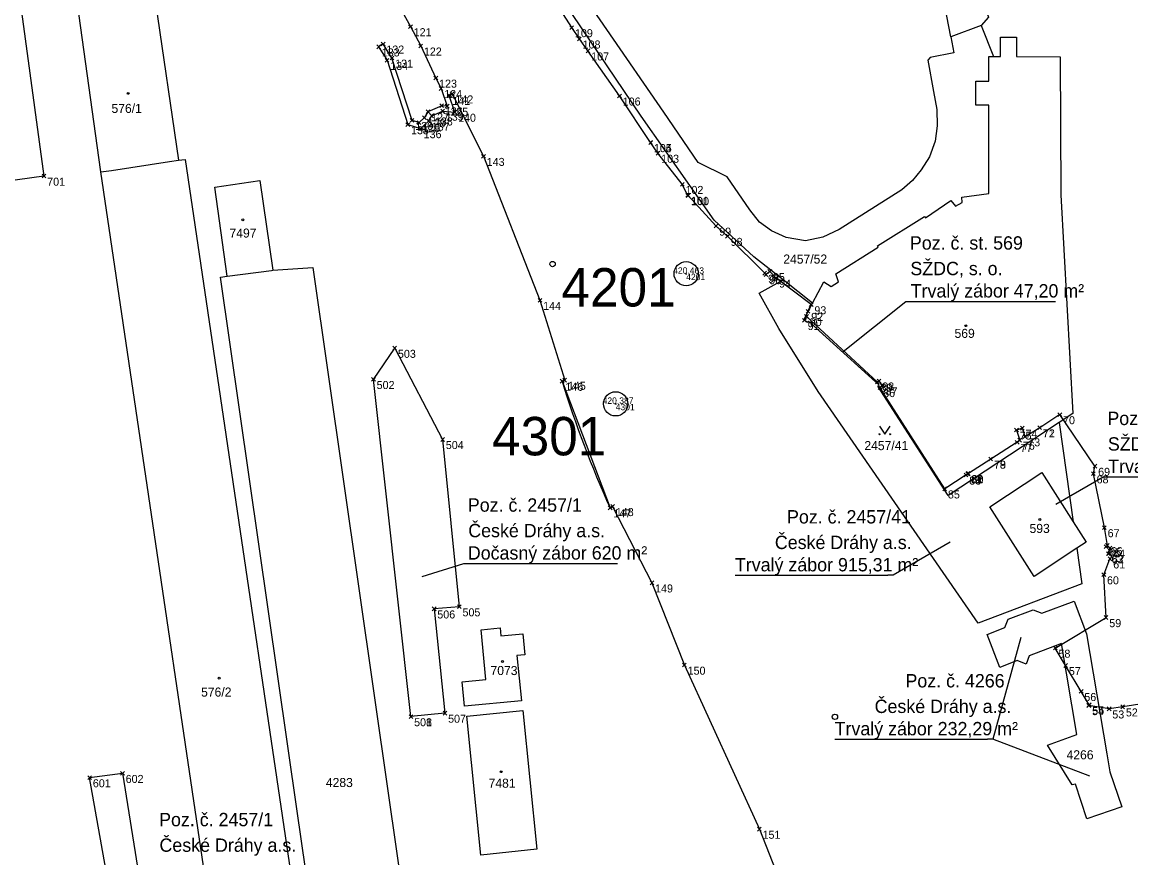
# Model space of a CAD drawing. Extents: x -667048 to -665920, y -1108425 to -1107247.
# Drawn here: x -666746.8 to -666539, y -1107757.1 to -1107600.6 of the extents above; entities that cross this region are included whole.
import ezdxf

# ---------------------------------------------------------------- set-up
doc = ezdxf.new("R2010")
doc.units = 0
for name, color, linetype in [('_JC - Obvod stavby - Přesunutá', 7, 'Continuous'), ('Default', 7, 'Continuous'), ('Hranice parcel', 7, 'Continuous'), ('JC - Popisky', 7, 'Continuous'), ('Parcelní čísla', 7, 'Continuous'), ('RK - body obvod stavby trvaly zabor', 7, 'Continuous'), ('RK-body obvod stavby docasny zabor', 7, 'Continuous'), ('RK-hektometry', 7, 'Continuous'), ('Vrstva 1', 7, 'Continuous'), ('Vrstva 60', 7, 'Continuous'), ('Vrstva 61', 7, 'Continuous'), ('Značky budov', 7, 'Continuous'), ('Značky kultur', 7, 'Continuous')]:
    doc.layers.add(name, color=color, linetype=linetype)

# ---------------------------------------------------------------- blocks, each defined once
blk = doc.blocks.new('4.021')
at = {"layer": 'Default'}
blk.add_circle((-7, 1), 175, dxfattribs=at)
blk = doc.blocks.new('3.141')
at = {"layer": 'Default'}
blk.add_lwpolyline([(-1000, 1500), (0, 0), (1000, 1500)], dxfattribs=at)
for centre in [(-1000, 0), (1000, 0)]:
    blk.add_circle(centre, 100, dxfattribs=at)
blk = doc.blocks.new('POINT_DISPLAY')
at = {"layer": 'Default'}
for p, q in [((-354, 354), (354, -354)), ((354, 354), (-354, -354))]:
    blk.add_line(p, q, dxfattribs=at)

msp = doc.modelspace()

# ---------------------------------------------------------------- linework, layer by layer
at = {"layer": '_JC - Obvod stavby - Přesunutá'}
for points in [[(-666742.73, -1107629.44), (-666752.71, -1107630.84), (-666760.26, -1107573.13), (-666748.86, -1107584.37)], [(-666673.95, -1107730.69), (-666680.97, -1107667.52), (-666676.98, -1107661.68), (-666668.01, -1107678.77), (-666664.88, -1107710.1), (-666669.6, -1107710.5), (-666667.58, -1107730.03), (-666673.95, -1107730.69)], [(-666734.17, -1107742.12), (-666728.02, -1107741.31), (-666718.84, -1107798.76), (-666727.43, -1107779.96)]]:
    msp.add_lwpolyline(points, close=True, dxfattribs=at)
for points in [[(-666543.16, -1107700.18), (-666543.24, -1107700.15), (-666542.9, -1107699.09), (-666543.67, -1107698.84), (-666543.39, -1107698.62), (-666543.95, -1107695.28), (-666546.02, -1107685.19), (-666545.73, -1107683.78), (-666552.31, -1107674.11), (-666556.09, -1107676.57), (-666556.08, -1107676.57), (-666558.83, -1107678.26), (-666559.34, -1107676.66), (-666560.44, -1107677.01), (-666559.84, -1107678.9), (-666560.3, -1107679.29), (-666565.26, -1107682.45), (-666565.26, -1107682.45), (-666569.46, -1107685.14), (-666569.46, -1107685.14), (-666569.57, -1107685.2), (-666569.9, -1107685.41), (-666569.89, -1107685.42), (-666573.89, -1107688.02), (-666586.03, -1107669.03), (-666585.57, -1107668.71), (-666586.2, -1107667.8), (-666586.51, -1107668.02), (-666599.79, -1107655.72), (-666600.18, -1107656.47), (-666599.52, -1107654.76), (-666598.92, -1107653.52), (-666605.53, -1107648.52), (-666606.68, -1107647.31), (-666607.38, -1107647.89), (-666607.62, -1107647.62), (-666614.61, -1107640.71), (-666616.76, -1107638.79), (-666622.01, -1107633.09), (-666622.08, -1107633.02), (-666623.08, -1107630.98), (-666627.64, -1107625.14), (-666629.01, -1107623.16), (-666629.01, -1107623.15), (-666634.85, -1107614.42), (-666640.76, -1107605.98), (-666642.36, -1107603.74), (-666643.8, -1107601.62), (-666649.87, -1107592.13)], [(-666676.9, -1107596.18), (-666674.03, -1107601.43), (-666672.12, -1107605.06), (-666669.27, -1107611.07), (-666668.3, -1107613.02), (-666667.16, -1107616.34), (-666668.18, -1107616.26), (-666670.75, -1107617.37), (-666671.43, -1107618.49), (-666672.42, -1107619.41), (-666673.74, -1107619), (-666677.5, -1107607.32), (-666679.16, -1107604.69), (-666680.01, -1107605.22), (-666678.42, -1107607.75), (-666674.53, -1107619.8), (-666672.16, -1107620.54), (-666670.64, -1107619.13), (-666670.06, -1107618.16), (-666668.01, -1107617.27), (-666665.71, -1107617.46), (-666666.8, -1107614.32), (-666666.21, -1107614.03), (-666660.34, -1107625.73), (-666649.76, -1107652.7), (-666645.12, -1107667.67), (-666645.6, -1107667.86)], [(-666677.5, -1107607.32), (-666679.16, -1107604.69), (-666680.01, -1107605.22), (-666678.42, -1107607.75), (-666674.53, -1107619.8), (-666672.16, -1107620.54), (-666670.64, -1107619.13), (-666670.06, -1107618.16), (-666668.01, -1107617.27), (-666665.71, -1107617.46), (-666666.8, -1107614.32), (-666666.21, -1107614.03), (-666664.47, -1107617.49), (-666660.34, -1107625.73), (-666649.76, -1107652.7), (-666645.12, -1107667.67), (-666645.6, -1107667.86), (-666636.61, -1107691.58), (-666636.14, -1107691.33), (-666628.78, -1107705.63), (-666622.68, -1107721.03), (-666608.64, -1107751.77)], [(-666512.22, -1107747.27), (-666521.36, -1107688.03), (-666528.3, -1107689.09), (-666531.26, -1107689.54), (-666530.04, -1107697.46), (-666535, -1107698.22), (-666530.52, -1107727.3), (-666540.53, -1107728.85), (-666543.07, -1107729.23), (-666546.87, -1107728.61), (-666546.82, -1107728.47), (-666548.32, -1107725.97), (-666551.22, -1107721.11), (-666553.17, -1107717.85), (-666543.64, -1107712.13), (-666544.07, -1107704.1), (-666542.91, -1107701.13)], [(-666636.61, -1107691.58), (-666636.14, -1107691.33), (-666628.78, -1107705.63), (-666622.68, -1107721.03), (-666608.64, -1107751.77), (-666598.56, -1107777.43), (-666571.77, -1107824.89), (-666555.68, -1107814.6), (-666495.19, -1107909.12)]]:
    msp.add_lwpolyline(points, dxfattribs=at)
for centre, radius, start, end in [((-666461.35, -1107611.56), 192.66, 196.9895, 204.5377), ((-666543.13, -1107700.68), 0.5, 295.521, 93.3455)]:
    msp.add_arc(centre, radius, start, end, dxfattribs=at)
at = {"layer": 'Hranice parcel'}
for points in [[(-666630.76, -1107618.23), (-666658.09, -1107577.77), (-666691.28, -1107525.7), (-666693.11, -1107522.85)], [(-666572.76, -1107603.37), (-666578.87, -1107571.61), (-666583.8, -1107572.39)], [(-666572.76, -1107603.37), (-666572.19, -1107606.37), (-666576.61, -1107607.21), (-666577.04, -1107607.73), (-666575.97, -1107613.58), (-666575.38, -1107616.98), (-666575.31, -1107620.02), (-666575.69, -1107622.9), (-666576.75, -1107625.82), (-666578.29, -1107628.27), (-666579.96, -1107630.28), (-666581.93, -1107631.99), (-666593.65, -1107639.44), (-666596.76, -1107640.9), (-666600, -1107641.55), (-666603.6, -1107640.92), (-666606.39, -1107639.71), (-666608.58, -1107638.07), (-666610.44, -1107635.78), (-666614.66, -1107629.56), (-666620.11, -1107626.87), (-666626.57, -1107617.45), (-666647.93, -1107586.45)], [(-666732.05, -1107628.66), (-666736.22, -1107598.97), (-666721.8, -1107596.97), (-666717.54, -1107626.48)], [(-666566.17, -1107598.29), (-666565.66, -1107599.66), (-666567.03, -1107601.25)], [(-666567.03, -1107601.25), (-666572.76, -1107603.37)], [(-666567.03, -1107601.25), (-666564.74, -1107607.02)], [(-666564.74, -1107607.02), (-666563.41, -1107607.03), (-666563.41, -1107603.43), (-666560.46, -1107603.44), (-666560.46, -1107607.04), (-666552.22, -1107607.08), (-666552.11, -1107632.97), (-666549.85, -1107673.9), (-666552.42, -1107675.59)], [(-666598.65, -1107653.22), (-666596.54, -1107649.23), (-666595.19, -1107650.15), (-666593.8, -1107649.26), (-666594.3, -1107647.74), (-666586.38, -1107642.75), (-666586.52, -1107642.5), (-666577.65, -1107637.02), (-666577.51, -1107637.27), (-666572.74, -1107634), (-666571.86, -1107635.1), (-666570.63, -1107634.38), (-666570.71, -1107633.36), (-666565.59, -1107632.71), (-666565.59, -1107616.15), (-666568.03, -1107616.14), (-666568.03, -1107611.65), (-666565.59, -1107611.66), (-666565.59, -1107607.02), (-666564.74, -1107607.02)], [(-666604.18, -1107648.89), (-666609.7, -1107644.56), (-666617.12, -1107637.69), (-666630.76, -1107618.23)], [(-666717.54, -1107626.48), (-666716.29, -1107626.3), (-666689.11, -1107810.01), (-666692.08, -1107810.45), (-666702.89, -1107812.05), (-666704.87, -1107812.34), (-666732.05, -1107628.66)], [(-666732.05, -1107628.66), (-666730.07, -1107628.38), (-666719.18, -1107626.72), (-666717.54, -1107626.48)], [(-666708.37, -1107648.2), (-666710.73, -1107631.52), (-666702.25, -1107630.28), (-666699.81, -1107647.09)], [(-666699.81, -1107647.09), (-666692.33, -1107646.53), (-666678.06, -1107745.89), (-666663.85, -1107844.88), (-666680.98, -1107847.35), (-666695.25, -1107748.37), (-666709.66, -1107648.37), (-666708.37, -1107648.2)], [(-666708.37, -1107648.2), (-666700.08, -1107647.11), (-666699.81, -1107647.09)], [(-666549.13, -1107699.14), (-666548.2, -1107705.83), (-666567.63, -1107713.19), (-666597.62, -1107669.8), (-666604.98, -1107658), (-666608.69, -1107651.38), (-666604.18, -1107648.89)], [(-666598.65, -1107653.22), (-666604.18, -1107648.89)], [(-666552.42, -1107675.59), (-666573.22, -1107689.24), (-666586.42, -1107668.8), (-666586.18, -1107668.63), (-666599.44, -1107656.61), (-666599.64, -1107656.86), (-666600.3, -1107656.35), (-666598.65, -1107653.22)], [(-666552.42, -1107675.59), (-666549.83, -1107694.17)], [(-666549.13, -1107699.14), (-666557.11, -1107704.42), (-666565.43, -1107691.4), (-666555.71, -1107684.96), (-666549.83, -1107694.17)], [(-666549.83, -1107694.17), (-666547.39, -1107697.99), (-666549.13, -1107699.14)], [(-666557.28, -1107710.66), (-666555.66, -1107711.33), (-666549.64, -1107709.03), (-666547.34, -1107715.16), (-666543.49, -1107737.65), (-666542.93, -1107741.03), (-666540.67, -1107747.56), (-666547.26, -1107749.85), (-666549.4, -1107743.32), (-666550.01, -1107743.47), (-666554.64, -1107736.05), (-666549.12, -1107734.02), (-666551.98, -1107716.99), (-666558.03, -1107719.33), (-666558.63, -1107720.85), (-666560.28, -1107720.2), (-666563.56, -1107721.47), (-666565.96, -1107715.28), (-666562.62, -1107714), (-666561.97, -1107712.45), (-666557.28, -1107710.66)], [(-666657.08, -1107715.56), (-666653, -1107715.16), (-666652.6, -1107719.1), (-666654.07, -1107719.25), (-666653.23, -1107727.71), (-666663.92, -1107728.7), (-666664.34, -1107724.16), (-666659.93, -1107723.75), (-666660.79, -1107714.43), (-666657.23, -1107714.08), (-666657.08, -1107715.56)], [(-666652.99, -1107729.54), (-666650.37, -1107755.53), (-666660.87, -1107756.61), (-666663.46, -1107730.6), (-666652.99, -1107729.54)]]:
    msp.add_lwpolyline(points, dxfattribs=at)
at = {"layer": 'JC - Popisky'}
for p, q in [((-666581.2, -1107652.91), (-666580.2, -1107652.91)), ((-666544.19, -1107685.77), (-666543.19, -1107685.77)), ((-666664.06, -1107702), (-666663.06, -1107702)), ((-666583.54, -1107704.21), (-666584.54, -1107704.21)), ((-666564.85, -1107734.93), (-666565.85, -1107734.93))]:
    msp.add_line(p, q, dxfattribs=at)
for points in [[(-666592.95, -1107662.3), (-666581.2, -1107652.91)], [(-666580.2, -1107652.91), (-666553.14, -1107652.91)], [(-666553.08, -1107690.91), (-666544.19, -1107685.77)], [(-666543.19, -1107685.77), (-666514.57, -1107685.77)], [(-666572.84, -1107698.03), (-666583.54, -1107704.21)], [(-666671.83, -1107704.46), (-666664.06, -1107702)], [(-666663.06, -1107702), (-666635.22, -1107702)], [(-666613.16, -1107704.21), (-666584.54, -1107704.21)], [(-666559.63, -1107715.89), (-666564.85, -1107734.93)], [(-666594.46, -1107734.93), (-666565.85, -1107734.93)], [(-666546.71, -1107741.82), (-666564.85, -1107734.93)]]:
    msp.add_lwpolyline(points, dxfattribs=at)
at = {"layer": 'RK-hektometry'}
for centre in [(-666647.4, -1107645.91), (-666594.46, -1107730.72)]:
    msp.add_circle(centre, 0.5, dxfattribs=at)
at = {"layer": 'Vrstva 1'}
for p, q in [((-666622.5, -1107647.73), (-666622.2, -1107647.73)), ((-666635.72, -1107672.1), (-666635.42, -1107672.1))]:
    msp.add_line(p, q, dxfattribs=at)
for centre in [(-666622.35, -1107647.73), (-666635.57, -1107672.1)]:
    msp.add_circle(centre, 2.27, dxfattribs=at)
at = {"layer": 'Vrstva 60'}
for p, q in [((-666622.35, -1107647.73), (-666622.35, -1107647.73)), ((-666635.57, -1107672.1), (-666635.57, -1107672.1))]:
    msp.add_line(p, q, dxfattribs=at)

# ---------------------------------------------------------------- block references
at = {"layer": 'RK - body obvod stavby trvaly zabor', "xscale": 0.0010000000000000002, "yscale": 0.0010000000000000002}
for p in [(-666674.03, -1107601.43), (-666643.8, -1107601.62), (-666642.36, -1107603.74), (-666680.01, -1107605.22), (-666679.16, -1107604.69), (-666672.12, -1107605.06), (-666640.76, -1107605.98), (-666678.42, -1107607.75), (-666677.5, -1107607.32), (-666669.27, -1107611.07), (-666668.3, -1107613.02), (-666666.8, -1107614.32), (-666666.21, -1107614.03), (-666668.18, -1107616.26), (-666667.16, -1107616.34), (-666634.85, -1107614.42), (-666670.75, -1107617.37), (-666670.06, -1107618.16), (-666668.01, -1107617.27), (-666665.71, -1107617.46), (-666674.53, -1107619.8), (-666673.74, -1107619), (-666672.42, -1107619.41), (-666672.16, -1107620.54), (-666671.43, -1107618.49), (-666670.64, -1107619.13), (-666629.01, -1107623.15), (-666629.01, -1107623.16), (-666660.34, -1107625.73), (-666627.64, -1107625.14), (-666623.08, -1107630.98), (-666622.08, -1107633.02), (-666622.01, -1107633.09), (-666616.76, -1107638.79), (-666614.61, -1107640.71), (-666606.68, -1107647.31), (-666607.62, -1107647.62), (-666607.38, -1107647.89), (-666605.53, -1107648.52), (-666649.76, -1107652.7), (-666598.92, -1107653.52), (-666599.79, -1107655.72), (-666599.52, -1107654.76), (-666600.18, -1107656.47), (-666645.6, -1107667.86), (-666645.12, -1107667.67), (-666586.51, -1107668.02), (-666586.2, -1107667.8), (-666586.03, -1107669.03), (-666585.57, -1107668.71), (-666552.31, -1107674.11), (-666559.34, -1107676.66), (-666556.09, -1107676.57), (-666556.08, -1107676.57), (-666560.44, -1107677.01), (-666558.83, -1107678.26), (-666560.3, -1107679.29), (-666559.84, -1107678.9), (-666565.26, -1107682.45), (-666565.26, -1107682.45), (-666545.73, -1107683.78), (-666569.9, -1107685.41), (-666569.89, -1107685.42), (-666569.57, -1107685.2), (-666569.46, -1107685.14), (-666569.46, -1107685.14), (-666546.02, -1107685.19), (-666573.89, -1107688.02), (-666636.61, -1107691.58), (-666636.14, -1107691.33), (-666543.95, -1107695.28), (-666543.67, -1107698.84), (-666543.39, -1107698.62), (-666542.9, -1107699.09), (-666543.24, -1107700.15), (-666543.16, -1107700.18), (-666542.91, -1107701.13), (-666628.78, -1107705.63), (-666544.07, -1107704.1), (-666543.64, -1107712.13), (-666553.17, -1107717.85), (-666622.68, -1107721.03), (-666551.22, -1107721.11), (-666548.32, -1107725.97), (-666546.87, -1107728.61), (-666546.82, -1107728.47), (-666543.07, -1107729.23), (-666540.53, -1107728.85), (-666608.64, -1107751.77)]:
    msp.add_blockref('POINT_DISPLAY', p, dxfattribs=at)
at = {"layer": 'RK-body obvod stavby docasny zabor', "xscale": 0.0010000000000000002, "yscale": 0.0010000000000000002}
for p in [(-666742.73, -1107629.44), (-666676.98, -1107661.68), (-666680.97, -1107667.52), (-666668.01, -1107678.77), (-666669.6, -1107710.5), (-666664.88, -1107710.1), (-666673.95, -1107730.69), (-666673.95, -1107730.69), (-666667.58, -1107730.03), (-666734.17, -1107742.12), (-666728.02, -1107741.31)]:
    msp.add_blockref('POINT_DISPLAY', p, dxfattribs=at)
at = {"layer": 'Značky budov', "xscale": 0.0010000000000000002, "yscale": 0.0010000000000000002}
for p in [(-666726.96, -1107613.94), (-666705.45, -1107637.62), (-666569.92, -1107657.46), (-666556.05, -1107693.75), (-666656.79, -1107720.35), (-666709.87, -1107723.49), (-666657.04, -1107741.01)]:
    msp.add_blockref('4.021', p, dxfattribs=at)
at = {"layer": 'Značky kultur', "xscale": 0.0010000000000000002, "yscale": 0.0010000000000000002}
msp.add_blockref('3.141', (-666585.13, -1107677.79), dxfattribs=at)

# ---------------------------------------------------------------- texts
at = {"layer": 'JC - Popisky'}
for s, p in [('Poz. č. st. 569', (-666580.42, -1107643.21)), ('SŽDC, s. o.', (-666580.33, -1107648)), ('Trvalý zábor 47,20 m²', (-666580.27, -1107652.18)), ('Poz. č. st. 593', (-666543.4, -1107676.07)), ('SŽDC, s. o.', (-666543.31, -1107680.86)), ('Trvalý zábor 180,13 m²', (-666543.25, -1107685.04)), ('Poz. č. 2457/1', (-666663.28, -1107692.3)), ('Poz. č. 2457/41', (-666603.45, -1107694.51)), ('České Dráhy a.s.', (-666663.2, -1107697.09)), ('České Dráhy a.s.', (-666605.73, -1107699.3)), ('Dočasný zábor 620 m²', (-666663.28, -1107701.27)), ('Trvalý zábor 915,31 m²', (-666613.22, -1107703.48)), ('Poz. č. 4266', (-666581.25, -1107725.22)), ('České Dráhy a.s.', (-666587.03, -1107730.01)), ('Trvalý zábor 232,29 m²', (-666594.53, -1107734.19)), ('Poz. č. 2457/1', (-666721.15, -1107751.22)), ('České Dráhy a.s.', (-666721.08, -1107756.01))]:
    msp.add_text(s, height=2.5, dxfattribs=at).set_placement(p)
at = {"layer": 'Parcelní čísla'}
for s, p in [('576/1', (-666730.08, -1107617.61)), ('7497', (-666707.95, -1107640.96)), ('2457/52', (-666604.15, -1107645.83)), ('569', (-666572.05, -1107659.75)), ('2457/41', (-666588.95, -1107680.77)), ('593', (-666557.99, -1107696.29)), ('7073', (-666659.03, -1107722.9)), ('576/2', (-666713.28, -1107726.94)), ('4266', (-666551.05, -1107738.69)), ('4283', (-666689.89, -1107743.88)), ('7481', (-666659.39, -1107744.01))]:
    msp.add_text(s, height=1.7, dxfattribs=at).set_placement(p)
at = {"layer": 'RK - body obvod stavby trvaly zabor'}
for s, p in [('121', (-666673.43, -1107603.23)), ('109', (-666643.2, -1107603.42)), ('133', (-666679.41, -1107607.02)), ('132', (-666678.56, -1107606.49)), ('122', (-666671.52, -1107606.86)), ('108', (-666641.76, -1107605.54)), ('131', (-666676.9, -1107609.12)), ('107', (-666640.16, -1107607.78)), ('134', (-666677.82, -1107609.55)), ('123', (-666668.67, -1107612.87)), ('124', (-666667.7, -1107614.82)), ('141', (-666666.2, -1107616.12)), ('142', (-666665.61, -1107615.83)), ('106', (-666634.25, -1107616.22)), ('127', (-666670.15, -1107619.17)), ('126', (-666667.58, -1107618.06)), ('139', (-666667.41, -1107619.07)), ('125', (-666666.56, -1107618.14)), ('140', (-666665.11, -1107619.26)), ('135', (-666673.93, -1107621.6)), ('130', (-666673.14, -1107620.8)), ('129', (-666671.82, -1107621.21)), ('128', (-666670.83, -1107620.29)), ('137', (-666670.04, -1107620.93)), ('138', (-666669.46, -1107619.96)), ('136', (-666671.56, -1107622.34)), ('104', (-666628.41, -1107624.96)), ('105', (-666628.41, -1107624.95)), ('143', (-666659.74, -1107627.53)), ('103', (-666627.04, -1107626.94)), ('102', (-666622.48, -1107632.78)), ('101', (-666621.48, -1107634.82)), ('100', (-666621.41, -1107634.89)), ('99', (-666616.16, -1107640.59)), ('98', (-666614.01, -1107642.51)), ('97', (-666607.02, -1107649.42)), ('96', (-666606.78, -1107649.69)), ('95', (-666606.08, -1107649.11)), ('94', (-666604.93, -1107650.32)), ('144', (-666649.16, -1107654.5)), ('92', (-666598.92, -1107656.56)), ('93', (-666598.32, -1107655.32)), ('91', (-666599.58, -1107658.27)), ('90', (-666599.19, -1107657.52)), ('145', (-666644.52, -1107669.47)), ('146', (-666645, -1107669.66)), ('89', (-666585.91, -1107669.82)), ('88', (-666585.6, -1107669.6)), ('86', (-666585.43, -1107670.83)), ('87', (-666584.97, -1107670.51)), ('70', (-666551.71, -1107675.91)), ('75', (-666559.84, -1107678.81)), ('74', (-666558.74, -1107678.46)), ('72', (-666555.48, -1107678.37)), ('71', (-666555.49, -1107678.37)), ('77', (-666559.7, -1107681.09)), ('76', (-666559.24, -1107680.7)), ('73', (-666558.23, -1107680.06)), ('78', (-666564.66, -1107684.25)), ('79', (-666564.66, -1107684.25)), ('69', (-666545.13, -1107685.58)), ('83', (-666569.3, -1107687.21)), ('84', (-666569.29, -1107687.22)), ('82', (-666568.97, -1107687)), ('80', (-666568.86, -1107686.94)), ('81', (-666568.86, -1107686.94)), ('68', (-666545.42, -1107686.99)), ('85', (-666573.29, -1107689.82)), ('147', (-666636.01, -1107693.38)), ('148', (-666635.54, -1107693.13)), ('67', (-666543.35, -1107697.08)), ('65', (-666543.07, -1107700.64)), ('66', (-666542.79, -1107700.42)), ('63', (-666542.64, -1107701.95)), ('62', (-666542.56, -1107701.98)), ('64', (-666542.3, -1107700.89)), ('61', (-666542.31, -1107702.93)), ('60', (-666543.47, -1107705.9)), ('149', (-666628.18, -1107707.43)), ('59', (-666543.04, -1107713.93)), ('58', (-666552.57, -1107719.65)), ('150', (-666622.08, -1107722.83)), ('57', (-666550.62, -1107722.91)), ('56', (-666547.72, -1107727.77)), ('54', (-666546.27, -1107730.41)), ('55', (-666546.22, -1107730.27)), ('53', (-666542.47, -1107731.03)), ('52', (-666539.93, -1107730.65)), ('151', (-666608.04, -1107753.57))]:
    msp.add_text(s, height=1.5, dxfattribs=at).set_placement(p)
at = {"layer": 'RK-body obvod stavby docasny zabor'}
for s, p in [('701', (-666742.13, -1107631.24)), ('503', (-666676.38, -1107663.48)), ('502', (-666680.37, -1107669.32)), ('504', (-666667.41, -1107680.57)), ('506', (-666669, -1107712.3)), ('505', (-666664.28, -1107711.9)), ('507', (-666666.98, -1107731.83)), ('501', (-666673.35, -1107732.49)), ('508', (-666673.35, -1107732.49)), ('601', (-666733.57, -1107743.92)), ('602', (-666727.42, -1107743.11))]:
    msp.add_text(s, height=1.5, dxfattribs=at).set_placement(p)
at = {"layer": 'Vrstva 1'}
for s, p in [('4201', (-666645.74, -1107653.87)), ('4301', (-666658.74, -1107681.75))]:
    msp.add_text(s, height=7.2, dxfattribs=at).set_placement(p)
at = {"layer": 'Vrstva 60'}
for s, p in [('4201', (-666622.35, -1107648.93)), ('4301', (-666635.57, -1107673.3))]:
    msp.add_text(s, height=1.2, dxfattribs=at).set_placement(p)
at = {"layer": 'Vrstva 61'}
for s, p in [('420.463', (-666624.8, -1107647.73)), ('420.387', (-666638.02, -1107672.1))]:
    msp.add_text(s, height=1.2, dxfattribs=at).set_placement(p)

doc.saveas('drawing.dxf')
